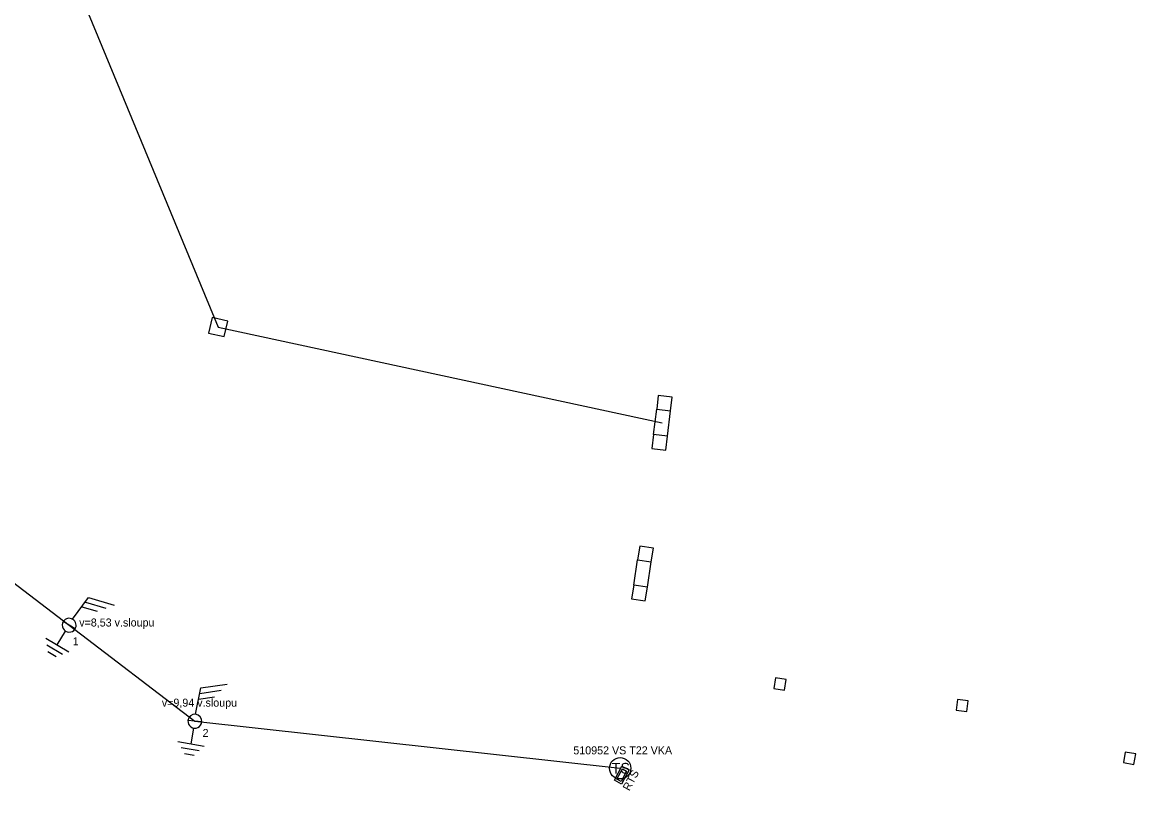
# Model space of a CAD drawing. Extents: x -536386 to -535479, y -1201638 to -1200910.
# Drawn here: x -536203.8 to -536099.4, y -1201311.9 to -1201239.9 of the extents above; entities that cross this region are included whole.
import ezdxf

# ---------------------------------------------------------------- set-up
doc = ezdxf.new("R2010")
doc.units = 0
for name, color, linetype in [('MAP_ZN_BP', 7, 'Continuous'), ('VÝŠKOPIS', 7, 'Continuous'), ('ZN_BP', 7, 'Continuous'), ('Č_POPIS_EVID', 7, 'Continuous')]:
    doc.layers.add(name, color=color, linetype=linetype)

msp = doc.modelspace()

# ---------------------------------------------------------------- linework, layer by layer
at = {"layer": 'MAP_ZN_BP'}
for p, q in [((-536144.6, -1201278.5), (-536144.31, -1201276.12)), ((-536143.31, -1201278.66), (-536143.02, -1201276.28)), ((-536146.46, -1201292.6), (-536146.1, -1201290.23)), ((-536145.18, -1201292.79), (-536144.82, -1201290.42)), ((-536199.04, -1201295.78), (-536197.55, -1201293.77)), ((-536197.84, -1201294.2), (-536195.92, -1201294.77)), ((-536197.55, -1201293.77), (-536195.15, -1201294.47)), ((-536198.17, -1201294.63), (-536196.73, -1201295.05)), ((-536198.81, -1201296.71), (-536199.91, -1201296.01)), ((-536200.47, -1201298.2), (-536199.69, -1201296.92)), ((-536201.54, -1201297.56), (-536199.39, -1201298.85)), ((-536201.45, -1201298.2), (-536199.99, -1201299.07)), ((-536201.37, -1201298.83), (-536200.59, -1201299.29)), ((-536187.53, -1201304.69), (-536187.03, -1201302.24)), ((-536187.11, -1201302.75), (-536185.13, -1201302.46)), ((-536187.03, -1201302.24), (-536184.56, -1201301.87)), ((-536187.23, -1201303.28), (-536185.75, -1201303.06)), ((-536186.93, -1201305.4), (-536188.23, -1201305.3)), ((-536187.94, -1201307.47), (-536187.69, -1201305.99)), ((-536189.17, -1201307.26), (-536186.7, -1201307.68)), ((-536188.86, -1201307.82), (-536187.18, -1201308.1)), ((-536188.55, -1201308.38), (-536187.66, -1201308.53))]:
    msp.add_line(p, q, dxfattribs=at)
for points in [[(-536312.75, -1200960.28), (-536249.32, -1201114.05), (-536185.4, -1201268.42), (-536143.81, -1201277.39)], [(-536227.12, -1201275.16), (-536199.36, -1201296.36), (-536187.58, -1201305.35), (-536147.73, -1201309.76)]]:
    msp.add_lwpolyline(points, dxfattribs=at)
for points in [[(-536186.3, -1201268.98), (-536184.84, -1201269.32), (-536184.5, -1201267.86), (-536185.96, -1201267.52)], [(-536144.31, -1201276.12), (-536143.02, -1201276.28), (-536142.87, -1201274.99), (-536144.16, -1201274.83)], [(-536144.75, -1201279.79), (-536143.46, -1201279.95), (-536143.31, -1201278.66), (-536144.6, -1201278.5)], [(-536146.1, -1201290.23), (-536144.82, -1201290.42), (-536144.62, -1201289.14), (-536145.9, -1201288.94)], [(-536146.66, -1201293.88), (-536145.38, -1201294.08), (-536145.18, -1201292.79), (-536146.46, -1201292.6)], [(-536148.26, -1201310.89), (-536147.56, -1201309.57), (-536146.9, -1201309.92), (-536147.6, -1201311.24)], [(-536148.04, -1201310.79), (-536147.52, -1201309.81), (-536147.13, -1201310.02), (-536147.64, -1201311)]]:
    msp.add_lwpolyline(points, close=True, dxfattribs=at)
msp.add_circle((-536147.73, -1201309.76), 1, dxfattribs=at)
for centre, start, end in [((-536199.36, -1201296.36), 147.6822, 327.6822), ((-536199.36, -1201296.36), 327.6822, 147.6822), ((-536187.58, -1201305.35), 355.1634, 175.1634), ((-536187.58, -1201305.35), 175.1634, 355.1634)]:
    msp.add_arc(centre, 0.65, start, end, dxfattribs=at)
at = {"layer": 'Č_POPIS_EVID'}
for p, q in [((-536133.17, -1201301.29), (-536133.32, -1201302.28)), ((-536132.18, -1201301.44), (-536133.17, -1201301.29)), ((-536132.33, -1201302.43), (-536132.18, -1201301.44)), ((-536133.32, -1201302.28), (-536132.33, -1201302.43)), ((-536116.13, -1201303.31), (-536116.25, -1201304.31)), ((-536115.13, -1201303.43), (-536116.13, -1201303.31)), ((-536115.25, -1201304.43), (-536115.13, -1201303.43)), ((-536116.25, -1201304.31), (-536115.25, -1201304.43)), ((-536100.41, -1201308.24), (-536100.58, -1201309.23)), ((-536099.42, -1201308.41), (-536100.41, -1201308.24)), ((-536099.59, -1201309.4), (-536099.42, -1201308.41)), ((-536100.58, -1201309.23), (-536099.59, -1201309.4))]:
    msp.add_line(p, q, dxfattribs=at)

# ---------------------------------------------------------------- texts
at = {"layer": 'MAP_ZN_BP'}
msp.add_text('TS', height=1, dxfattribs=at).set_placement((-536148.52, -1201310.26))
at = {"layer": 'VÝŠKOPIS'}
for s, p in [('v=8,53 v.sloupu', (-536198.42, -1201296.48)), ('v=9,94 v.sloupu', (-536190.68, -1201303.99))]:
    msp.add_text(s, height=0.75, dxfattribs=at).set_placement(p)
at = {"layer": 'ZN_BP'}
for s, p in [('1', (-536199.03, -1201298.24)), ('2', (-536186.86, -1201306.83)), ('510952 VS T22 VKA', (-536152.12, -1201308.46))]:
    msp.add_text(s, height=0.75, dxfattribs=at).set_placement(p)
msp.add_text('RTS', height=0.75, rotation=62.1104, dxfattribs=at).set_placement((-536146.87, -1201311.94))

doc.saveas('drawing.dxf')
